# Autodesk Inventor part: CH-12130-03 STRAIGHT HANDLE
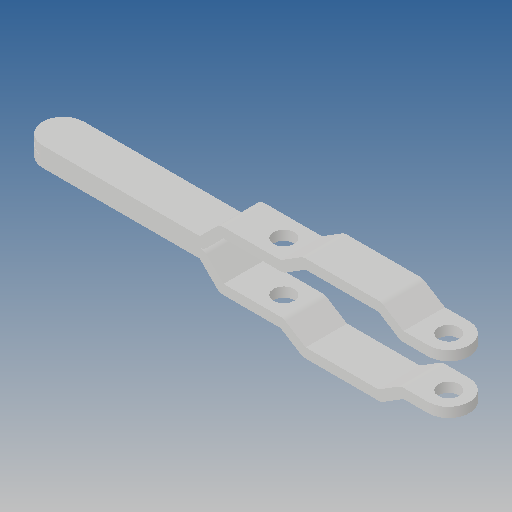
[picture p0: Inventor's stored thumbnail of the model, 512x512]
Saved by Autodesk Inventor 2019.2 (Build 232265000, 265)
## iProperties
Created: 2012-09
Part Number: CH-12130-03 STRAIGHT HANDLE
Material: Ogólny
Document SubType Name: Modeling
Designer: CADENGINEERING4
Density: 1 g/cm^3
Appearance: Domyślna
Author: CADENGINEERING4
Revision Number: ÈÎºÎ
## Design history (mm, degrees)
feature "ÇÐ³ý-À­Éì1"
feature "¾µÏò1"
node "Bryła1"
node "Bryła2"
